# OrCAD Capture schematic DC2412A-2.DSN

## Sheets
1 PAGE1: size Custom; rev: 1
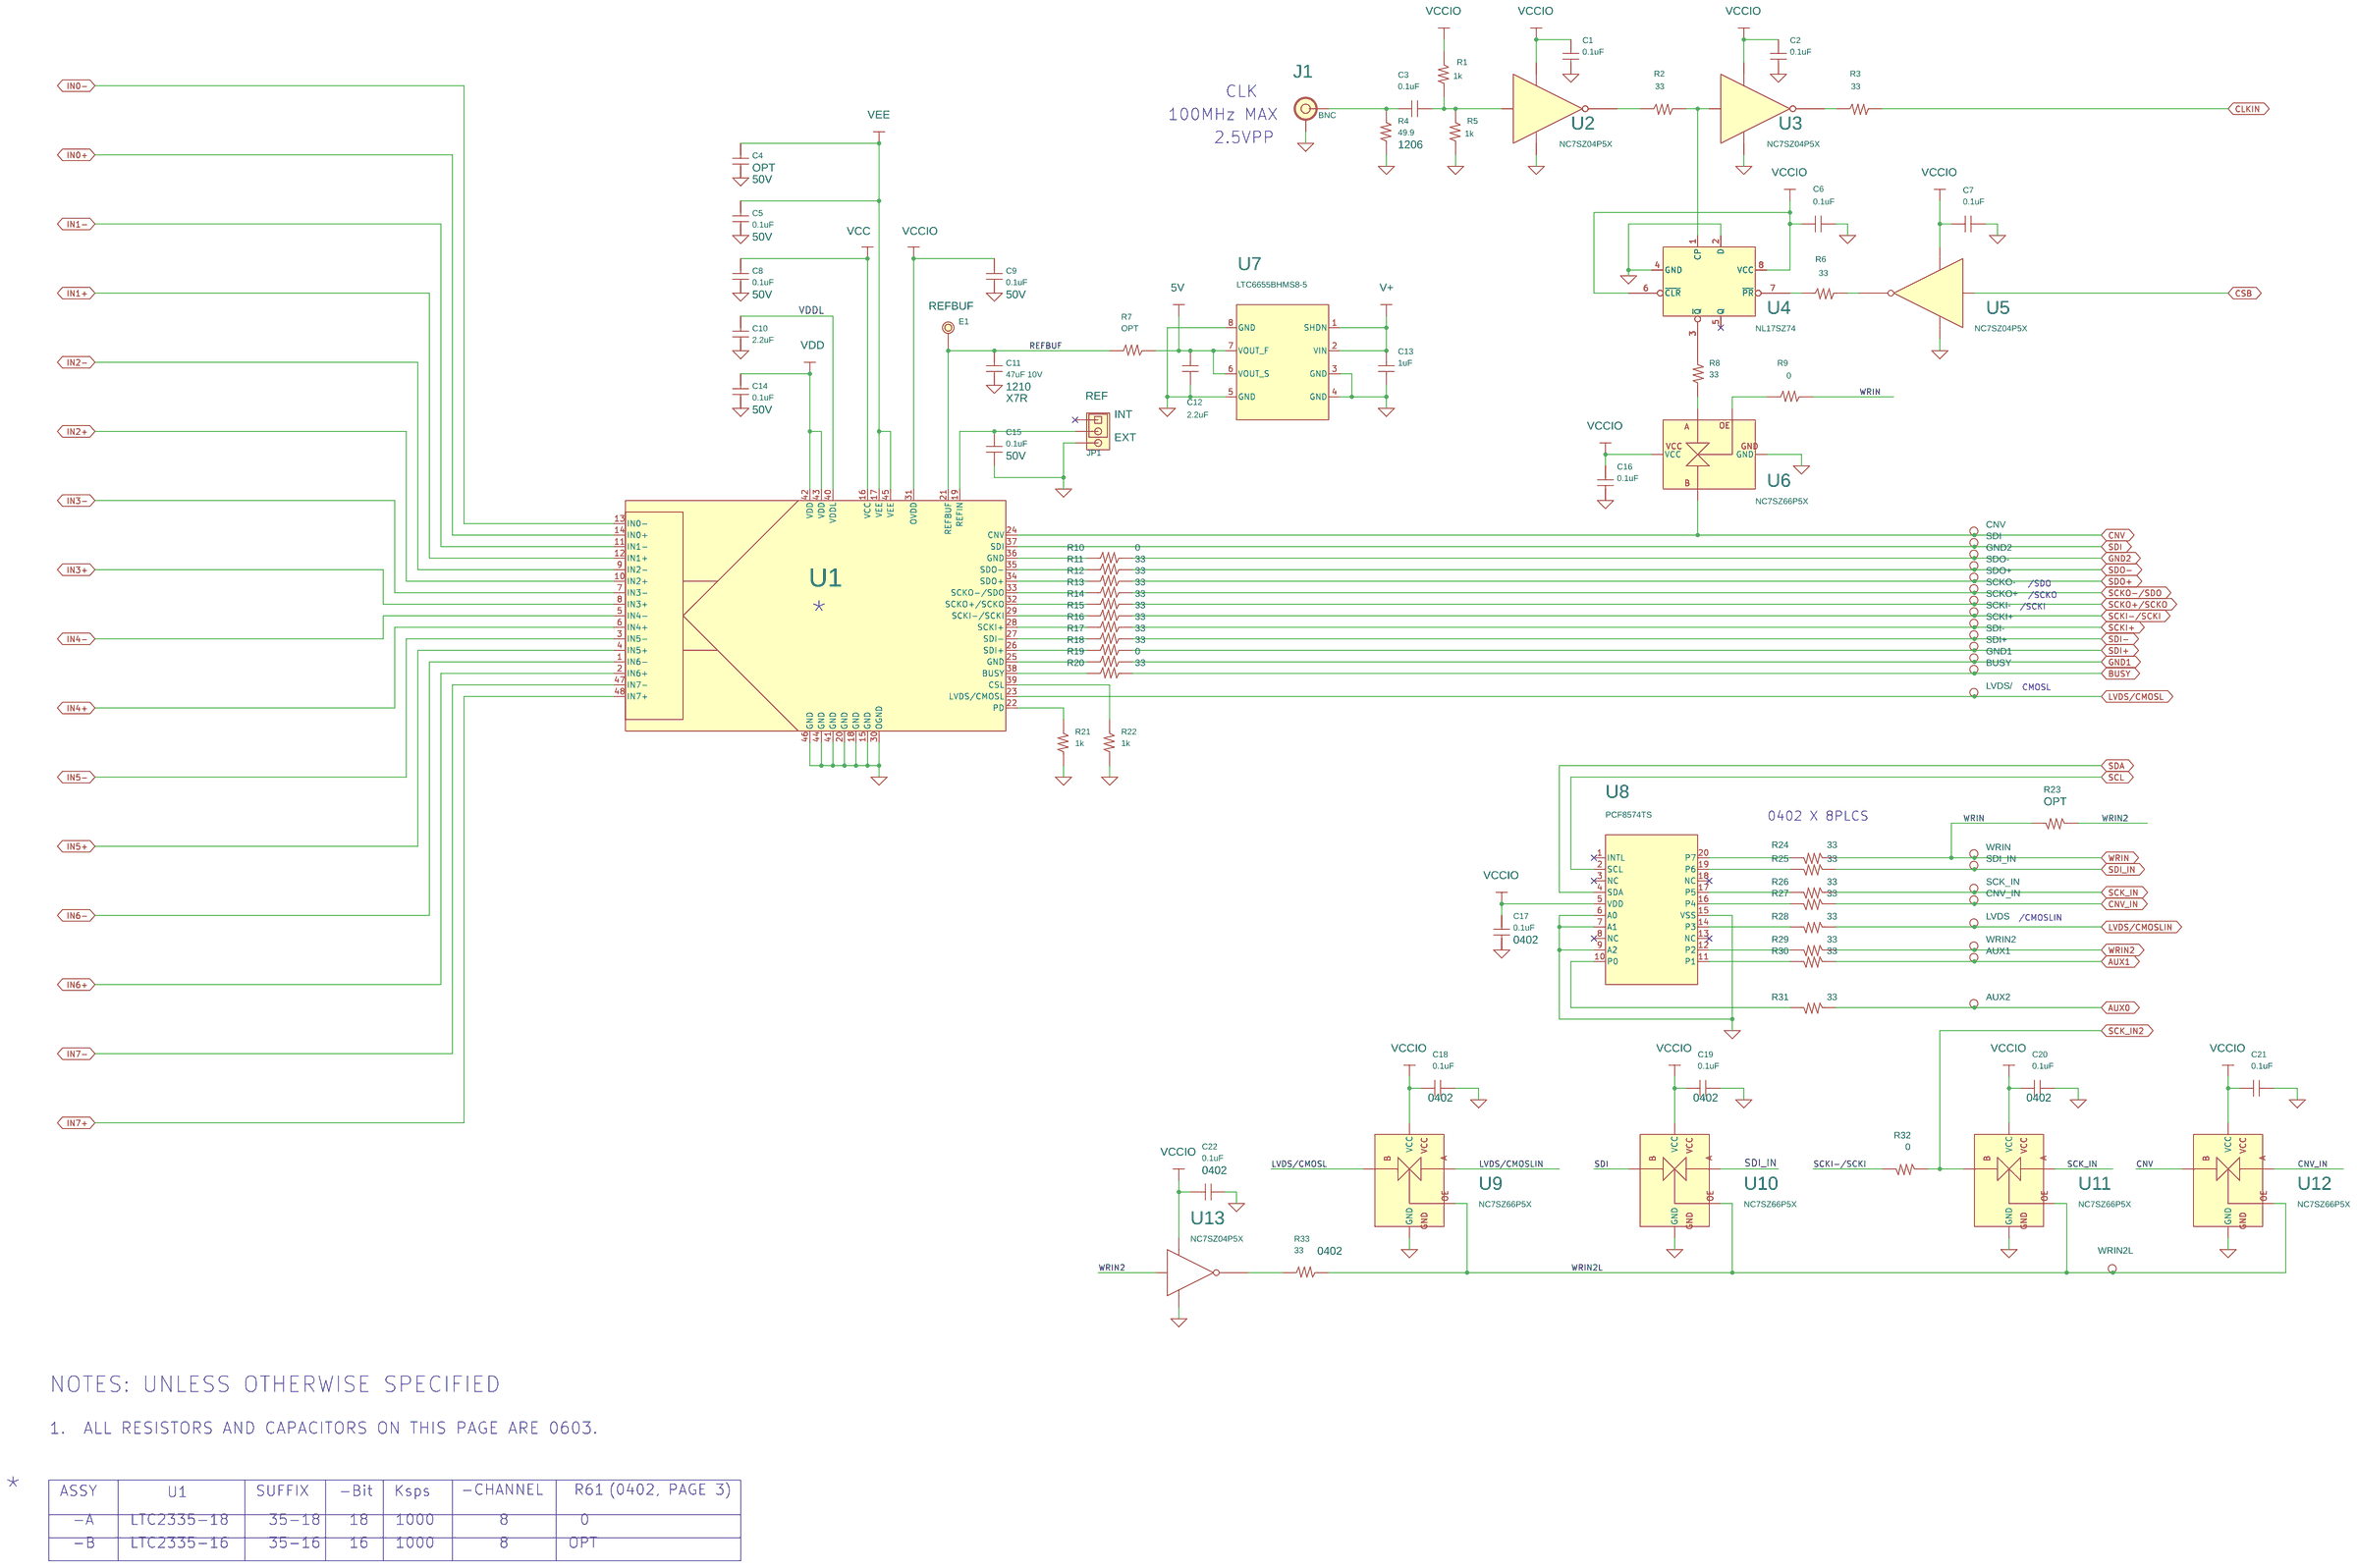
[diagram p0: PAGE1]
2 PAGE2: size B; title: 8-CHANNEL, SOFTSPAN, HIGH SPEED, SERIAL, SAR, ADC; rev: 2; company: LTC23XXILX  FAMILY; note: DEMO CIRCUIT 2412A; note: B
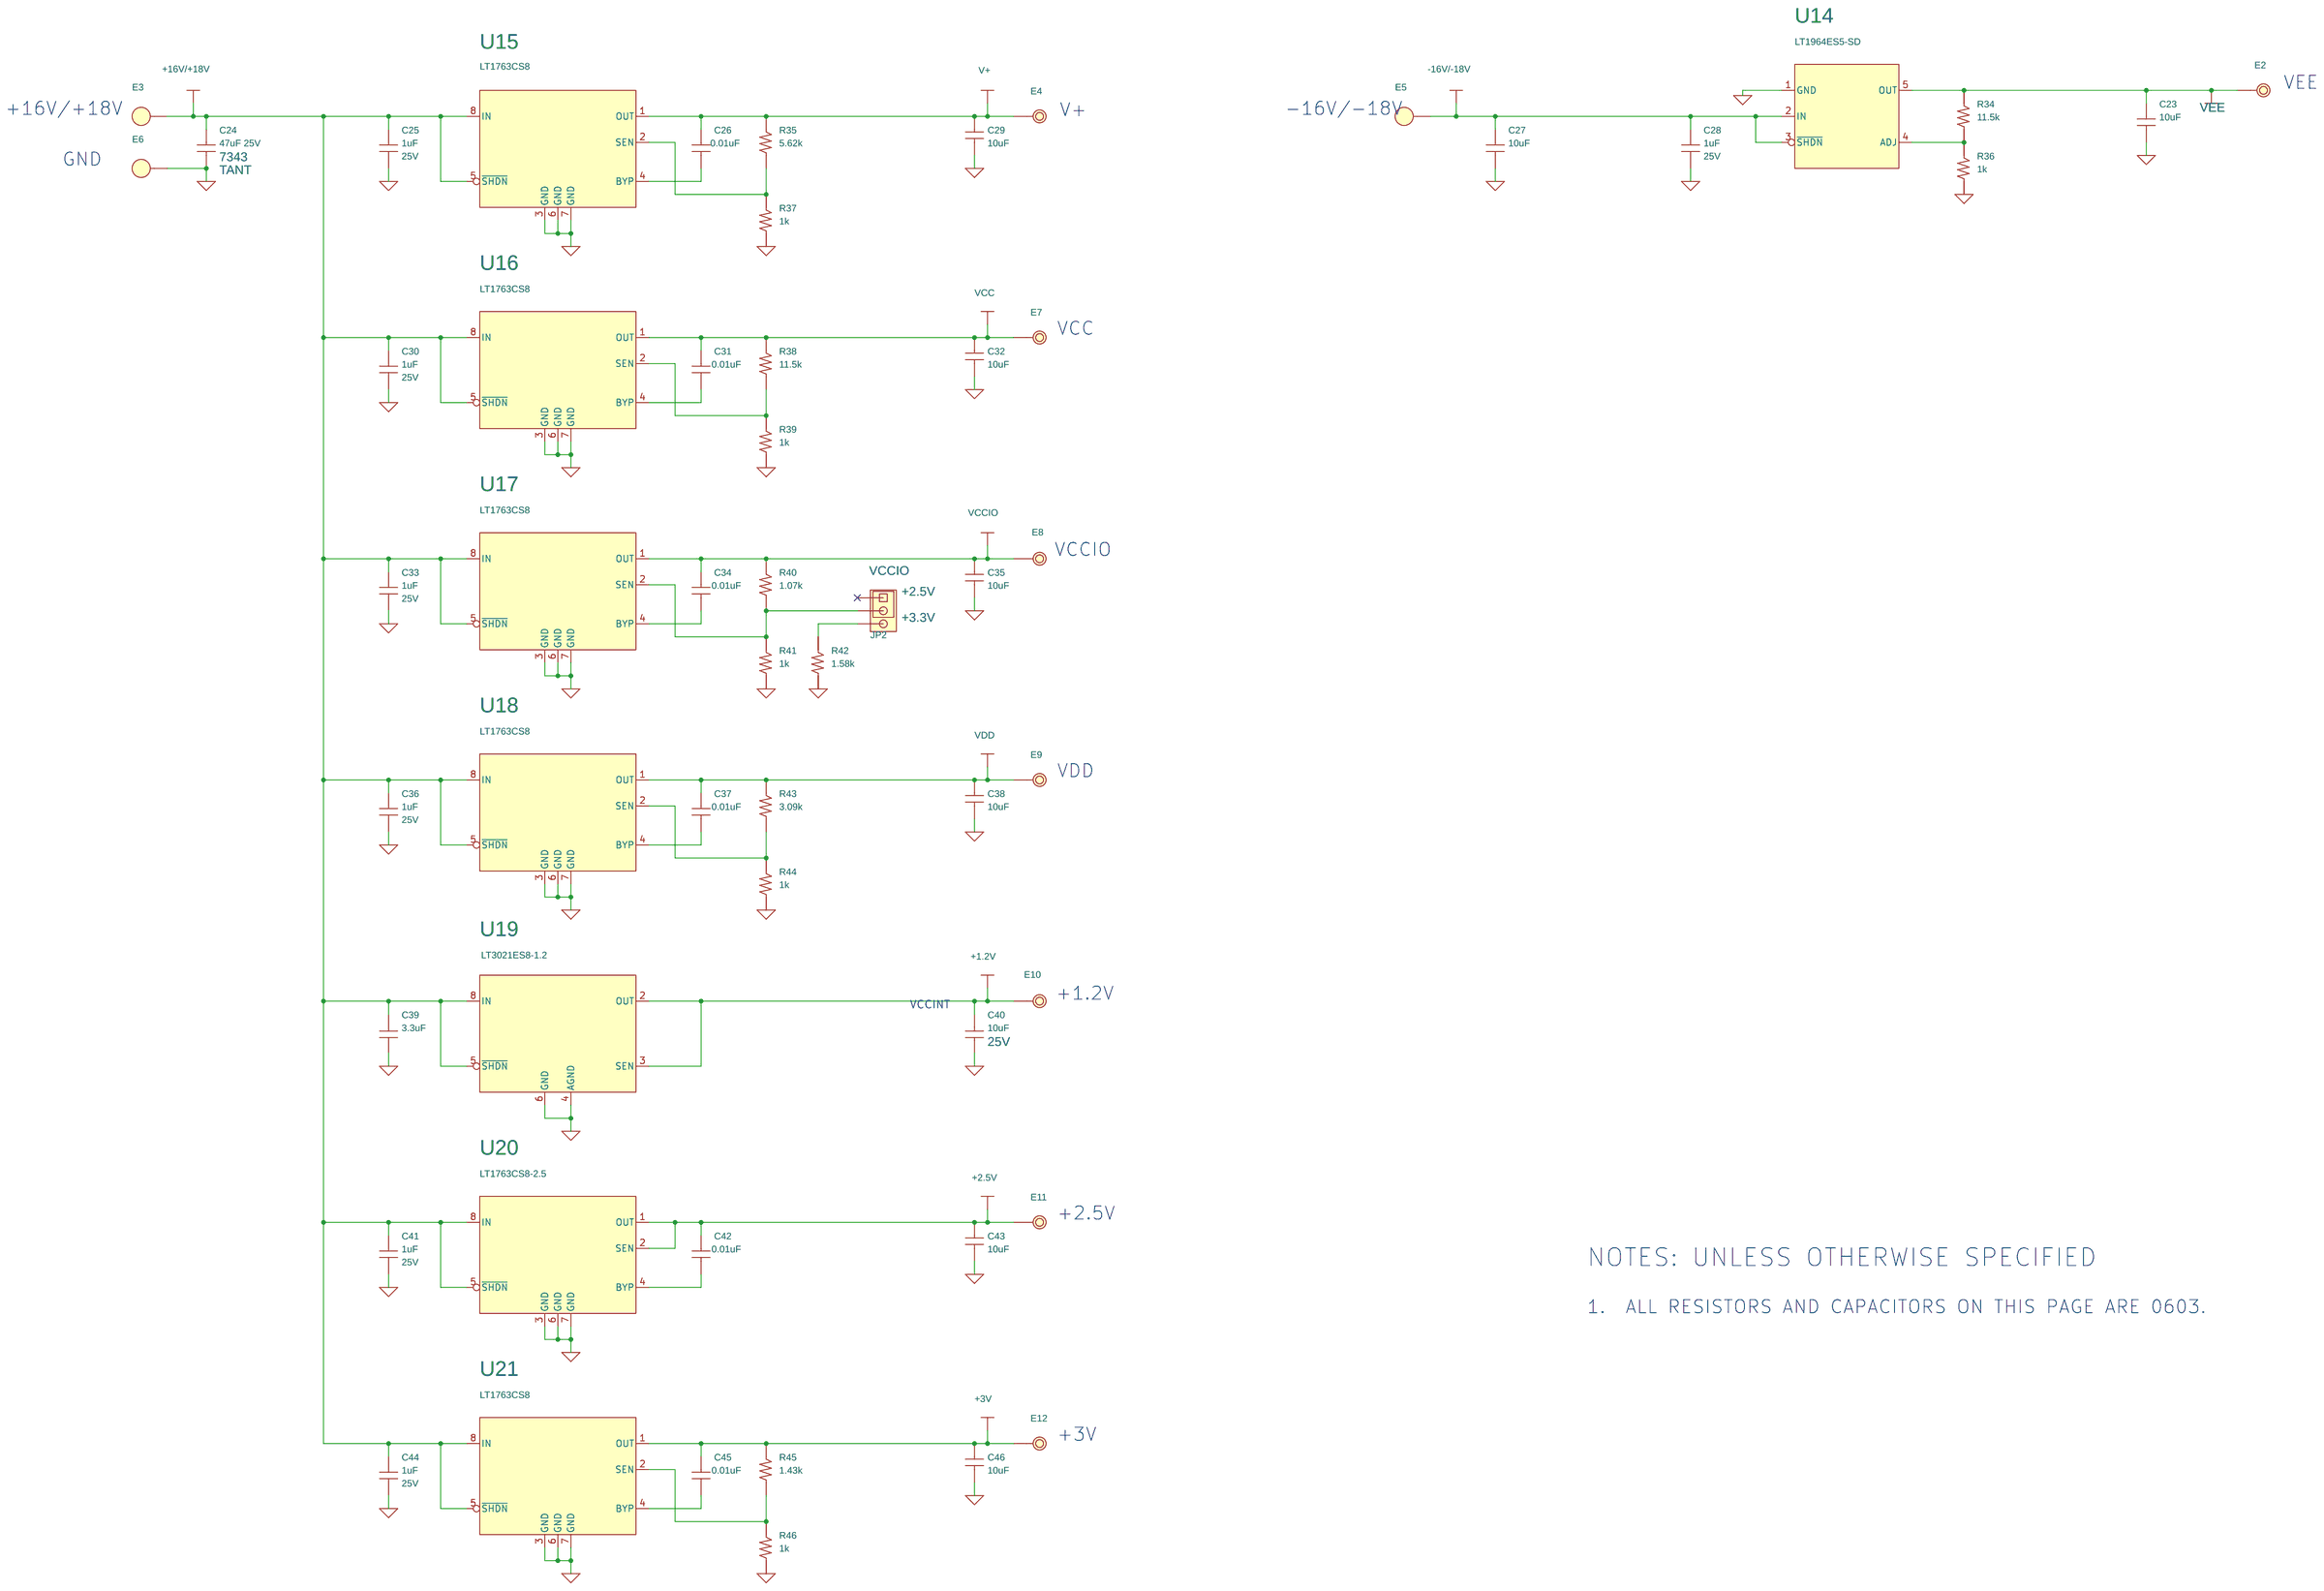
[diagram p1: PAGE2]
3 PAGE3: size B; title: 8-CHANNEL, SOFTSPAN, HIGH SPEED, SERIAL, SAR, ADC; rev: 2; company: LTC23XXILX  FAMILY; note: DEMO CIRCUIT 2412A; note: B
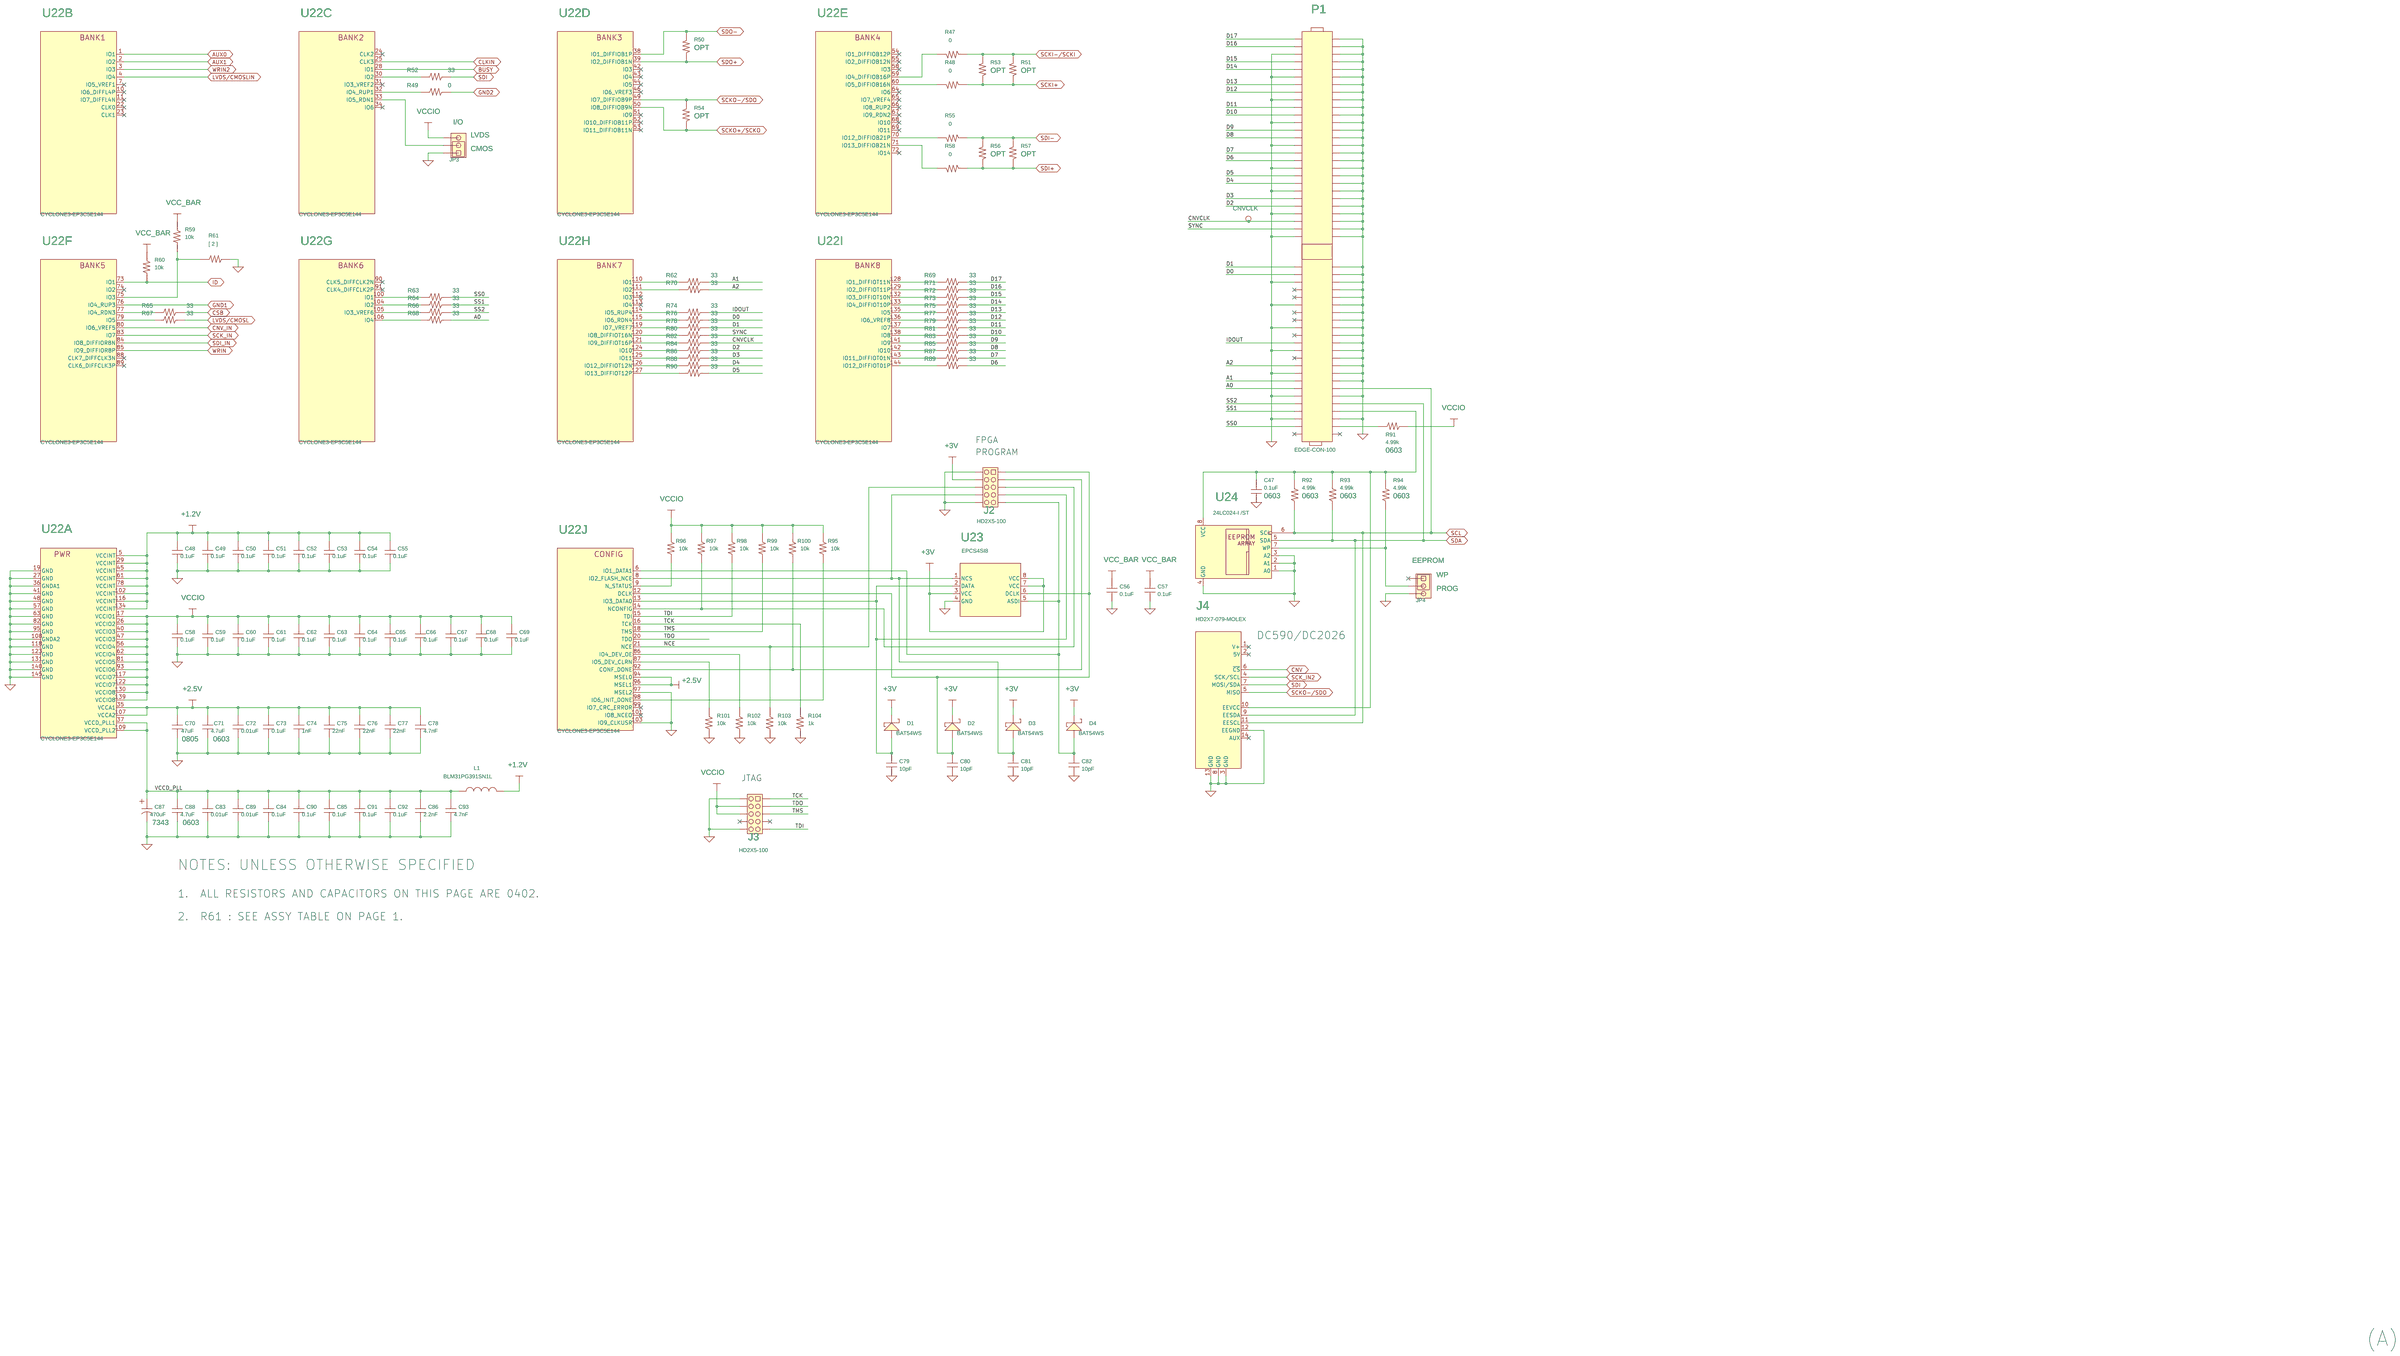
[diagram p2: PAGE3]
4 PAGE4: size B; title: 8-CHANNEL, SOFTSPAN, HIGH SPEED, SERIAL, SAR, ADC; rev: 2; company: LTC23XXILX  FAMILY; note: DEMO CIRCUIT 2412A; note: B
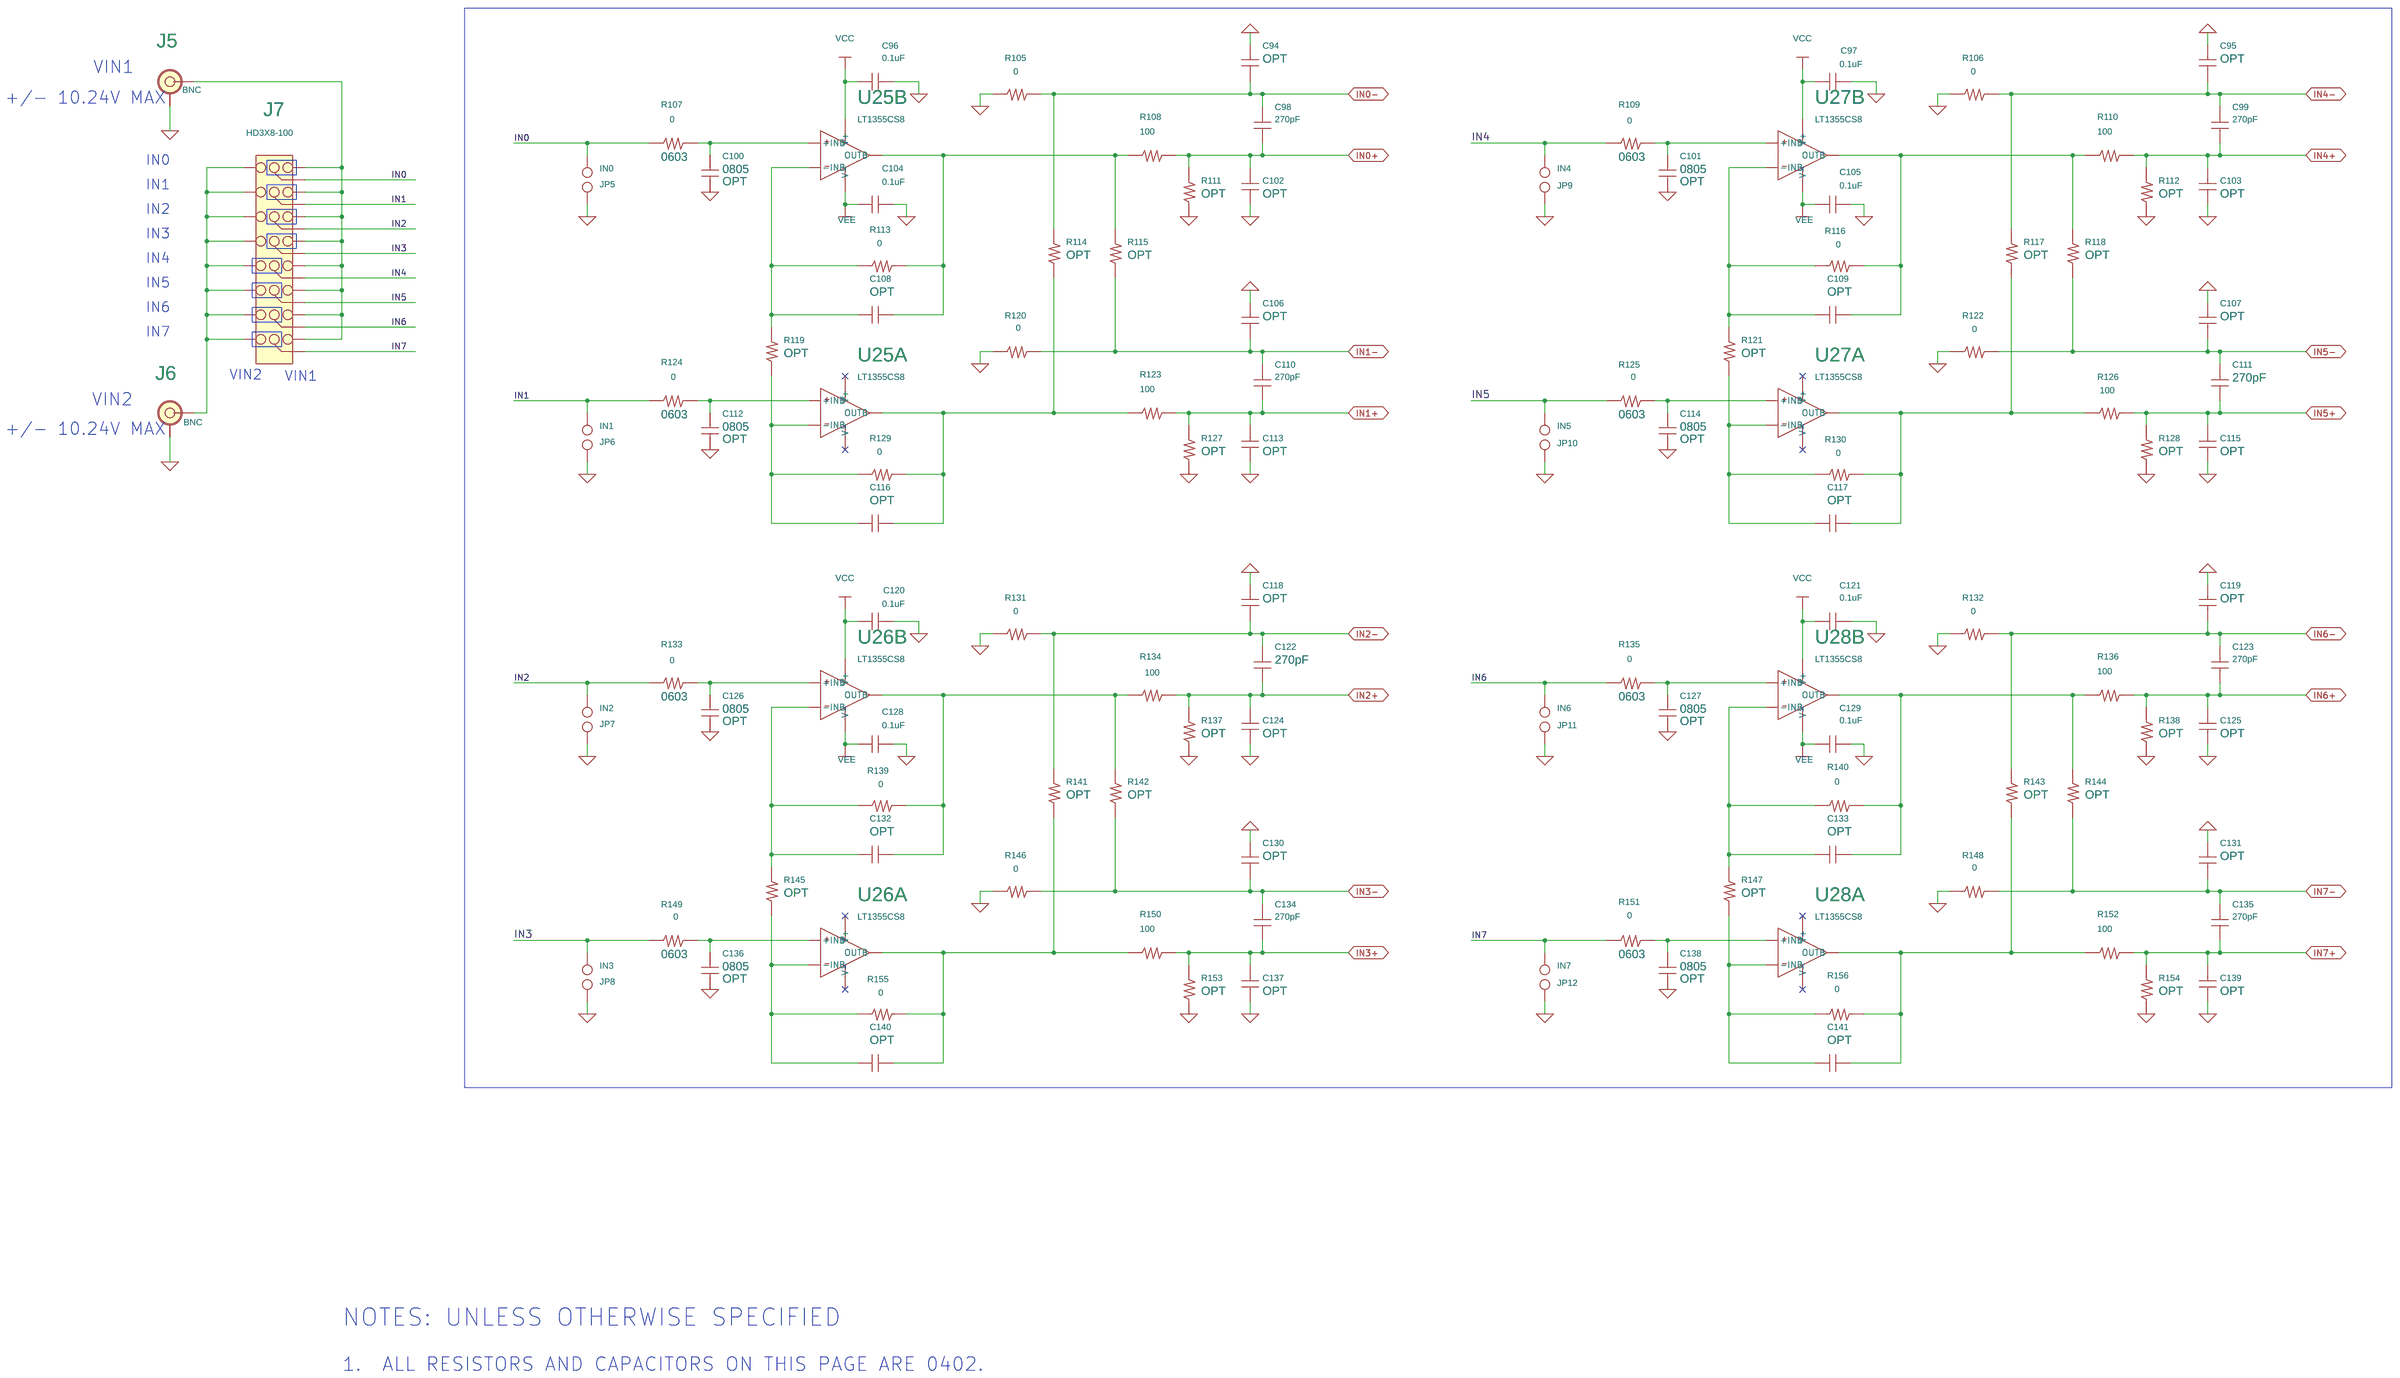
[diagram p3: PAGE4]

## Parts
sheet PAGE1
AUX1  PAD030-015-SQ  [PAD030-015-SQ]
AUX2  PAD030-015-SQ  [PAD030-015-SQ]
BUSY  PAD030-015-SQ  [PAD030-015-SQ]
C1  0.1uF  [0603]
C2  0.1uF  [0603]
C3  0.1uF  [0603]
C4  C-0603  [0603]
C5  0.1uF  [0603]
C6  0.1uF  [0603]
C7  0.1uF  [0603]
C8  0.1uF  [0603]
C9  0.1uF  [0603]
C10  2.2uF  [0603]
C11  47uF 10V  [1210]
C12  2.2uF  [0603]
C13  1uF  [0603]
C14  0.1uF  [0603]
C15  0.1uF  [0603]
C16  0.1uF  [0603]
C17  0.1uF  [0402]
C18  0.1uF  [0402]
C19  0.1uF  [0402]
C20  0.1uF  [0402]
C21  0.1uF  [0603]
C22  0.1uF  [0402]
CNV  PAD030-015-SQ  [PAD030-015-SQ]
CNV_IN  PAD030-015-SQ  [PAD030-015-SQ]
E1  MILL-MAX-2308  [MILL-MAX-2308]
GND1  PAD030-015-SQ  [PAD030-015-SQ]
GND2  PAD030-015-SQ  [PAD030-015-SQ]
J1  BNC  [BNC5]
JP1  HD1X3-100  [HD1X3-100]
LVDS  PAD030-015-SQ  [PAD030-015-SQ]
LVDS/  PAD030-015-SQ  [PAD030-015-SQ]
R1  1k  [0603]
R2  33  [0603]
R3  33  [0603]
R4  49.9  [1206]
R5  1k  [0603]
R6  33  [0603]
R7  OPT  [0603]
R8  33  [0603]
R9  0  [0603]
R10  0  [0603]
R11  33  [0603]
R12  33  [0603]
R13  33  [0603]
R14  33  [0603]
R15  33  [0603]
R16  33  [0603]
R17  33  [0603]
R18  33  [0603]
R19  0  [0603]
R20  33  [0603]
R21  1k  [0603]
R22  1k  [0603]
R23  R-0402  [0402]
R24  33  [0402]
R25  33  [0402]
R26  33  [0402]
R27  33  [0402]
R28  33  [0402]
R29  33  [0402]
R30  33  [0402]
R31  33  [0402]
R32  0  [0402]
R33  33  [0402]
SCK_IN  PAD030-015-SQ  [PAD030-015-SQ]
SCKI+  PAD030-015-SQ  [PAD030-015-SQ]
SCKI-  PAD030-015-SQ  [PAD030-015-SQ]
SCKO+  PAD030-015-SQ  [PAD030-015-SQ]
SCKO-  PAD030-015-SQ  [PAD030-015-SQ]
SDI  PAD030-015-SQ  [PAD030-015-SQ]
SDI+  PAD030-015-SQ  [PAD030-015-SQ]
SDI-  PAD030-015-SQ  [PAD030-015-SQ]
SDI_IN  PAD030-015-SQ  [PAD030-015-SQ]
SDO+  PAD030-015-SQ  [PAD030-015-SQ]
SDO-  PAD030-015-SQ  [PAD030-015-SQ]
U1  LTC2335  [LQFP48LX-7X7]
U2  NC7SZ04P5X  [SC70-5]
U3  NC7SZ04P5X  [SC70-5]
U4  NL17SZ74  [US8]
U5  NC7SZ04P5X  [SC70-5]
U6  NC7SZ66P5X  [SC70-5]
U7  LTC6655BHMS8-5  [MSOP8]
U8  PCF8574TS  [SSOP20]
U9  NC7SZ66P5X  [SC70-5]
U10  NC7SZ66P5X  [SC70-5]
U11  NC7SZ66P5X  [SC70-5]
U12  NC7SZ66P5X  [SC70-5]
U13  NC7SZ04P5X  [SC70-5]
WRIN  PAD030-015-SQ  [PAD030-015-SQ]
WRIN2  PAD030-015-SQ  [PAD030-015-SQ]
WRIN2L  PAD030-015-SQ  [PAD030-015-SQ]
sheet PAGE2
C23  10uF  [0603]
C24  47uF 25V  [7343]
C25  1uF  [0603]
C26  0.01uF  [0603]
C27  10uF  [0603]
C28  1uF  [0603]
C29  10uF  [0603]
C30  1uF  [0603]
C31  0.01uF  [0603]
C32  10uF  [0603]
C33  1uF  [0603]
C34  0.01uF  [0603]
C35  10uF  [0603]
C36  1uF  [0603]
C37  0.01uF  [0603]
C38  10uF  [0603]
C39  3.3uF  [0603]
C40  10uF  [0603]
C41  1uF  [0603]
C42  0.01uF  [0603]
C43  10uF  [0603]
C44  1uF  [0603]
C45  0.01uF  [0603]
C46  10uF  [0603]
E2  MILL-MAX-2308  [MILL-MAX-2308]
E3  MILL-MAX-2501  [MILL-MAX-2501]
E4  MILL-MAX-2308  [MILL-MAX-2308]
E5  MILL-MAX-2501  [MILL-MAX-2501]
E6  MILL-MAX-2501  [MILL-MAX-2501]
E7  MILL-MAX-2308  [MILL-MAX-2308]
E8  MILL-MAX-2308  [MILL-MAX-2308]
E9  MILL-MAX-2308  [MILL-MAX-2308]
E10  MILL-MAX-2308  [MILL-MAX-2308]
E11  MILL-MAX-2308  [MILL-MAX-2308]
E12  MILL-MAX-2308  [MILL-MAX-2308]
JP2  HD1X3-100  [HD1X3-100]
R34  11.5k  [0603]
R35  5.62k  [0603]
R36  1k  [0603]
R37  1k  [0603]
R38  11.5k  [0603]
R39  1k  [0603]
R40  1.07k  [0603]
R41  1k  [0603]
R42  1.58k  [0603]
R43  3.09k  [0603]
R44  1k  [0603]
R45  1.43k  [0603]
R46  1k  [0603]
U14  LT1964ES5-SD  [SOT23-S5]
U15  LT1763CS8  [SO8]
U16  LT1763CS8  [SO8]
U17  LT1763CS8  [SO8]
U18  LT1763CS8  [SO8]
U19  LT3021ES8-1.2  [SO8]
U20  LT1763CS8-2.5  [SO8]
U21  LT1763CS8  [SO8]
sheet PAGE3
C47  0.1uF  [0603]
C48  0.1uF  [0402]
C49  0.1uF  [0402]
C50  0.1uF  [0402]
C51  0.1uF  [0402]
C52  0.1uF  [0402]
C53  0.1uF  [0402]
C54  0.1uF  [0402]
C55  0.1uF  [0402]
C56  0.1uF  [0402]
C57  0.1uF  [0402]
C58  0.1uF  [0402]
C59  0.1uF  [0402]
C60  0.1uF  [0402]
C61  0.1uF  [0402]
C62  0.1uF  [0402]
C63  0.1uF  [0402]
C64  0.1uF  [0402]
C65  0.1uF  [0402]
C66  0.1uF  [0402]
C67  0.1uF  [0402]
C68  0.1uF  [0402]
C69  0.1uF  [0402]
C70  47uF  [0805]
C71  4.7uF  [0603]
C72  0.01uF  [0402]
C73  0.1uF  [0402]
C74  1nF  [0402]
C75  22nF  [0402]
C76  22nF  [0402]
C77  22nF  [0402]
C78  4.7nF  [0402]
C79  10pF  [0402]
C80  10pF  [0402]
C81  10pF  [0402]
C82  10pF  [0402]
C83  0.01uF  [0402]
C84  0.1uF  [0402]
C85  0.1uF  [0402]
C86  2.2nF  [0402]
C87  470uF  [7343]
C88  4.7uF  [0603]
C89  0.01uF  [0402]
C90  0.1uF  [0402]
C91  0.1uF  [0402]
C92  0.1uF  [0402]
C93  4.7nF  [0402]
CNVCLK  PAD030-015-SQ  [PAD030-015-SQ]
D1  BAT54WS  [SOD323]
D2  BAT54WS  [SOD323]
D3  BAT54WS  [SOD323]
D4  BAT54WS  [SOD323]
J2  HD2X5-100  [HD2X5-100]
J3  HD2X5-100  [HD2X5-100]
J4  HD2X7-079-MOLEX  [HD2X7-079-MOLEX]
JP3  HD1X3-100  [HD1X3-100]
JP4  HD1X3-100  [HD1X3-100]
L1  BLM31PG391SN1L  [1206]
P1  EDGE-CON-100  [CON-GOLD-100P-TB]
R47  0  [0402]
R48  0  [0402]
R49  0  [0402]
R50  R-0402  [0402]
R51  R-0402  [0402]
R52  33  [0402]
R53  R-0402  [0402]
R54  R-0402  [0402]
R55  0  [0402]
R56  R-0402  [0402]
R57  R-0402  [0402]
R58  0  [0402]
R59  10k  [0402]
R60  10k  [0402]
R61  [ 2 ]  [0402]
R62  33  [0402]
R63  33  [0402]
R64  33  [0402]
R65  33  [0402]
R66  33  [0402]
R67  33  [0402]
R68  33  [0402]
R69  33  [0402]
R70  33  [0402]
R71  33  [0402]
R72  33  [0402]
R73  33  [0402]
R74  33  [0402]
R75  33  [0402]
R76  33  [0402]
R77  33  [0402]
R78  33  [0402]
R79  33  [0402]
R80  33  [0402]
R81  33  [0402]
R82  33  [0402]
R83  33  [0402]
R84  33  [0402]
R85  33  [0402]
R86  33  [0402]
R87  33  [0402]
R88  33  [0402]
R89  33  [0402]
R90  33  [0402]
R91  4.99k  [0603]
R92  4.99k  [0603]
R93  4.99k  [0603]
R94  4.99k  [0603]
R95  10k  [0402]
R96  10k  [0402]
R97  10k  [0402]
R98  10k  [0402]
R99  10k  [0402]
R100  10k  [0402]
R101  10k  [0402]
R102  10k  [0402]
R103  10k  [0402]
R104  1k  [0402]
U22  CYCLONE3-EP3C5E144  [EQFP144]  (sections A,B,C,D,E,F,G,H,I,J)
U23  EPCS4SI8  [SO8]
U24  24LC024-I /ST  [TSSOP8]
sheet PAGE4
C94  C-0402  [0402]
C95  C-0402  [0402]
C96  0.1uF  [0402]
C97  0.1uF  [0402]
C98  270pF  [0402]
C99  270pF  [0402]
C100  C-0805  [0805]
C101  C-0805  [0805]
C102  C-0402  [0402]
C103  C-0402  [0402]
C104  0.1uF  [0402]
C105  0.1uF  [0402]
C106  C-0402  [0402]
C107  C-0402  [0402]
C108  C-0402  [0402]
C109  C-0402  [0402]
C110  270pF  [0402]
C111  270pF  [0402]
C112  C-0805  [0805]
C113  C-0402  [0402]
C114  C-0805  [0805]
C115  C-0402  [0402]
C116  C-0402  [0402]
C117  C-0402  [0402]
C118  C-0402  [0402]
C119  C-0402  [0402]
C120  0.1uF  [0402]
C121  0.1uF  [0402]
C122  270pF  [0402]
C123  270pF  [0402]
C124  C-0402  [0402]
C125  C-0402  [0402]
C126  C-0805  [0805]
C127  C-0805  [0805]
C128  0.1uF  [0402]
C129  0.1uF  [0402]
C130  C-0402  [0402]
C131  C-0402  [0402]
C132  C-0402  [0402]
C133  C-0402  [0402]
C134  270pF  [0402]
C135  270pF  [0402]
C136  C-0805  [0805]
C137  C-0402  [0402]
C138  C-0805  [0805]
C139  C-0402  [0402]
C140  C-0402  [0402]
C141  C-0402  [0402]
J5  BNC  [BNC5]
J6  BNC  [BNC5]
J7  HD3X8-100  [HD3X8-100]
JP5  HD1X2-100  [HD1X2-100]
JP6  HD1X2-100  [HD1X2-100]
JP7  HD1X2-100  [HD1X2-100]
JP8  HD1X2-100  [HD1X2-100]
JP9  HD1X2-100  [HD1X2-100]
JP10  HD1X2-100  [HD1X2-100]
JP11  HD1X2-100  [HD1X2-100]
JP12  HD1X2-100  [HD1X2-100]
R105  0  [0402]
R106  0  [0402]
R107  0  [0603]
R108  100  [0402]
R109  0  [0603]
R110  100  [0402]
R111  R-0402  [0402]
R112  R-0402  [0402]
R113  0  [0402]
R114  R-0402  [0402]
R115  R-0402  [0402]
R116  0  [0402]
R117  R-0402  [0402]
R118  R-0402  [0402]
R119  R-0402  [0402]
R120  0  [0402]
R121  R-0402  [0402]
R122  0  [0402]
R123  100  [0402]
R124  0  [0603]
R125  0  [0603]
R126  100  [0402]
R127  R-0402  [0402]
R128  R-0402  [0402]
R129  0  [0402]
R130  0  [0402]
R131  0  [0402]
R132  0  [0402]
R133  0  [0603]
R134  100  [0402]
R135  0  [0603]
R136  100  [0402]
R137  R-0402  [0402]
R138  R-0402  [0402]
R139  0  [0402]
R140  0  [0402]
R141  R-0402  [0402]
R142  R-0402  [0402]
R143  R-0402  [0402]
R144  R-0402  [0402]
R145  R-0402  [0402]
R146  0  [0402]
R147  R-0402  [0402]
R148  0  [0402]
R149  0  [0603]
R150  100  [0402]
R151  0  [0603]
R152  100  [0402]
R153  R-0402  [0402]
R154  R-0402  [0402]
R155  0  [0402]
R156  0  [0402]
U25  LT1355CS8  [SO8]  (sections A,B)
U26  LT1355CS8  [SO8]  (sections A,B)
U27  LT1355CS8  [SO8]  (sections A,B)
U28  LT1355CS8  [SO8]  (sections A,B)

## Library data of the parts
AUX1 AUX2 BUSY CNV CNV_IN CNVCLK GND1 GND2 LVDS LVDS/ SCK_IN SCKI+ SCKI- SCKO+ SCKO- SDI SDI+ SDI- SDI_IN SDO+ SDO- WRIN WRIN2 WRIN2L = E-HOLE
C1-C3 C6 C7 C10 C12 C13 C16-C22 C26 C31 C32 C34 C37 C39 C42 C45 C47-C86 C88-C93 C96-C99 C104 C105 C110 C111 C120-C123 C128 C129 C134 C135 = CAP-NP
C4 = CAP-NP: 1st Part Field: 50V; OPT: OPT
C5 C8 C9 C14 C15 = CAP-NP: 1st Part Field: 50V
C11 = CAP-NP: 1st Part Field: X7R
E1 = E-064: 1st Part Field: REFBUF
J1 = BNC: 1st Part Field: <1st Part Field>
JP1 = HD1X3: 1st Part Field: REF; 2nd Part Field: EXT; 3rd Part Field: INT
R1-R22 R24-R49 R52 R55 R58-R110 R113 R116 R120 R122-R126 R129-R136 R139 R140 R146 R148-R152 R155 R156 = R
R23 R50 R51 R53 R54 R56 R57 R111 R112 R114 R115 R117-R119 R121 R127 R128 R137 R138 R141-R145 R147 R153 R154 = R: OPT: OPT
U1 = LTC2335ILX-LQFP48LX-7X7
U2 U3 U5 = NC7SZ04P5X-ONE
U4 = NL17SZ74-US8
U6 U9-U12 = NC7SZ66P5X-SC70-5
U7 = LTC6655AHMSH-5
U8 = PCF8574TS-SSOP20
U13 = NC7SZ04P5X-SC70-5
C23 C25 C27-C30 C33 C35 C36 C38 C41 C43 C44 C46 = CAP-NP: 1ST PART FIELD: 25V
C24 = CAP-NP: 1ST PART FIELD: 16V; 2nd Part Field: TANT; 5TH PART FIELD: 1210
C40 = CAP-NP: 1st Part Field: 25V
E2 E4 E7-E12 = E-064
E3 E5 E6 = E-094
JP2 = HD1X3: 1st Part Field: VCCIO; 2nd Part Field: +3.3V; 3rd Part Field: +2.5V
U14 = LT1964ES5-SD-SOT23-5
U15-U18 U20 U21 = LT1763CS8-SO8
U19 = LT3021ES8-SO8
C87 = CAP
D1-D4 = BAT54WS-SOD323
J2 J3 = HD2X5-100_0
J4 = HD2X7-079-MOLEX
JP3 = HD1X3: 1st Part Field: I/O; 2nd Part Field: LVDS; 3rd Part Field: CMOS
JP4 = HD1X3: 1st Part Field: EEPROM; 2nd Part Field: PROG; 3rd Part Field: WP
L1 = IND
P1 = CON-EDGE-100P-TB
U22 = CYCLONE3-EP3C5E144-EQFP144
U23 = EPCS4SI8-SO8
U24 = 24LC025-I_ST
C94 C95 C100-C103 C106-C109 C112-C119 C124-C127 C130-C133 C136-C141 = CAP-NP: OPT: OPT
J5 J6 = BNC
J7 = HD3X8-100
JP5 = HD1X2-100: PART FIELD 1: IN0
JP6 = HD1X2-100: PART FIELD 1: IN1
JP7 = HD1X2-100: PART FIELD 1: IN2
JP8 = HD1X2-100: PART FIELD 1: IN3
JP9 = HD1X2-100: PART FIELD 1: IN4
JP10 = HD1X2-100: PART FIELD 1: IN5
JP11 = HD1X2-100: PART FIELD 1: IN6
JP12 = HD1X2-100: PART FIELD 1: IN7
U25-U28 = LT1355CS8-SO8

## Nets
5V: C12.2 R7.1 U7.6(VOUT_S) U7.7(VOUT_F)
+1.2V: C40.2 C48.2 C49.2 C50.2 C51.2 C52.2 C53.2 C54.2 C55.2 E10.1(A) L1.2 U19.2(OUT) U19.3(SEN) U22.5(VCCINT) U22.29(VCCINT) U22.45(VCCINT) U22.61(VCCINT) U22.78(VCCINT) U22.102(VCCINT) U22.116(VCCINT) U22.134(VCCINT)
+2.5V: C42.1 C43.1 C70.2 C71.2 C72.2 C73.2 C74.2 C75.2 C76.2 C77.2 C78.2 E11.1(A) U20.1(OUT) U20.2(SEN) U22.35(VCCA1) U22.94(MSEL0) U22.96(MSEL1) U22.107(VCCA2)
+3V: C45.1 C46.1 C56.2 C57.2 D1.1 D2.1 D3.1 D4.1 E12.1(A) J2.4 R45.1 U21.1(OUT) U23.3(VCC) U23.7(VCC) U23.8(VCC)
+16V/+18V: C24.1 C25.1 C30.1 C33.1 C36.1 C39.2 C41.1 C44.1 E3.1(A) U15.5(~{SHDN}) U15.8(IN) U16.5(~{SHDN}) U16.8(IN) U17.5(~{SHDN}) U17.8(IN) U18.5(~{SHDN}) U18.8(IN) U19.5(~{SHDN}) U19.8(IN) U20.5(~{SHDN}) U20.8(IN) U21.5(~{SHDN}) U21.8(IN)
-16V/-18V: C27.1 C28.1 E5.1(A) U14.2(IN) U14.3(~{SHDN})
GND: C1.2 C2.2 C4.1 C5.1 C6.2 C7.2 C8.1 C9.1 C10.1 C11.1 C12.1 C13.1 C14.1 C15.1 C16.2 C17.2 C18.2 C19.2 C20.2 C21.2 C22.1 C23.2 C24.2 C25.2 C27.2 C28.2 C29.2 C30.2 C32.2 C33.2 C35.2 C36.2 C38.2 C39.1 C40.1 C41.2 C43.2 C44.2 C46.2 C47.1 C48.1 C49.1 C50.1 C51.1 C52.1 C53.1 C54.1 C55.1 C56.1 C57.1 C58.1 C59.1 C60.1 C61.1 C62.1 C63.1 C64.1 C65.1 C66.1 C67.1 C68.1 C69.1 C70.1 C71.1 C72.1 C73.1 C74.1 C75.1 C76.1 C77.1 C78.1 C79.1 C80.1 C81.1 C82.1 C83.1 C84.1 C85.1 C86.1 C87.2 C88.1 C89.1 C90.1 C91.1 C92.1 C93.1 C94.1 C95.1 C96.2 C97.2 C100.2 C101.2 C102.1 C103.1 C104.2 C105.2 C106.1 C107.1 C112.2 C113.1 C114.2 C115.1 C118.1 C119.1 C120.2 C121.2 C124.1 C125.1 C126.2 C127.2 C128.2 C129.2 C130.1 C131.1 C136.2 C137.1 C138.2 C139.1 E6.1(A) J1.2 J1.3 J1.4 J1.5 J2.2 J2.10 J3.2 J3.10 J4.3(GND) J4.8(GND) J4.12(EEGND) J4.13(GND) J5.2 J5.3 J5.4 J5.5 J6.2 J6.3 J6.4 J6.5 JP1.3 JP3.1 JP4.3 JP5.2 JP6.2 JP7.2 JP8.2 JP9.2 JP10.2 JP11.2 JP12.2 P1.1 P1.3 P1.5 P1.6 P1.7 P1.9 P1.11 P1.12 P1.13 P1.15 P1.17 P1.18 P1.19 P1.21 P1.23 P1.24 P1.25 P1.27 P1.29 P1.30 P1.31 P1.33 P1.35 P1.36 P1.37 P1.39 P1.41 P1.42 P1.43 P1.45 P1.47 P1.48 P1.49 P1.51 P1.53 P1.54 P1.55 P1.57 P1.59 P1.60 P1.61 P1.63 P1.65 P1.66 P1.67 P1.69 P1.71 P1.72 P1.73 P1.75 P1.77 P1.78 P1.79 P1.81 P1.83 P1.84 P1.85 P1.89 P1.90 P1.95 P1.96 R4.2 R5.2 R21.2 R22.2 R36.2 R37.2 R39.2 R41.2 R42.2 R44.2 R46.2 R61.1 R101.2 R102.2 R103.2 R104.2 R105.1 R106.1 R111.1 R112.1 R120.1 R122.1 R127.1 R128.1 R131.1 R132.1 R137.1 R138.1 R146.1 R148.1 R153.1 R154.1 U1.15(GND) U1.18(GND) U1.20(GND) U1.30(OGND) U1.41(GND) U1.44(GND) U1.46(GND) U2.3 U3.3 U4.2(D) U4.4(GND) U5.3 U6.3(GND) U7.3(GND) U7.4(GND) U7.5(GND) U7.8(GND) U8.6(A0) U8.7(A1) U8.9(A2) U8.15(VSS) U9.3(GND) U10.3(GND) U11.3(GND) U12.3(GND) U13.3 U14.1(GND) U15.3(GND) U15.6(GND) U15.7(GND) U16.3(GND) U16.6(GND) U16.7(GND) U17.3(GND) U17.6(GND) U17.7(GND) U18.3(GND) U18.6(GND) U18.7(GND) U19.4(AGND) U19.6(GND) U20.3(GND) U20.6(GND) U20.7(GND) U21.3(GND) U21.6(GND) U21.7(GND) U22.19(GND) U22.27(GND) U22.36(GNDA1) U22.41(GND) U22.48(GND) U22.57(GND) U22.63(GND) U22.82(GND) U22.95(GND) U22.97(MSEL2) U22.103(IO9_CLKUSR) U22.108(GNDA2) U22.118(GND) U22.123(GND) U22.131(GND) U22.140(GND) U22.145(GND) U23.4(GND) U24.1(A0) U24.2(A1) U24.3(A2) U24.4(GND)
GND1: GND1.1 R19.1 U22.76(IO4_RUP3)
GND2: GND2.1 R10.1 R49.1
VCC: C8.2 C31.1 C32.1 C96.1 C97.1 C120.1 C121.1 E7.1(A) R38.1 U1.16(VCC) U16.1(OUT) U25.8(V+) U26.8(V+) U27.8(V+) U28.8(V+)
VCCD_PLL: C83.2 C84.2 C85.2 C86.2 C87.1 C88.2 C89.2 C90.2 C91.2 C92.2 C93.2 L1.1 U22.37(VCCD_PLL1) U22.109(VCCD_PLL2)
VCCIO: C1.1 C2.1 C6.1 C7.1 C9.2 C16.1 C17.1 C18.1 C19.1 C20.1 C21.1 C22.2 C34.1 C35.1 C58.2 C59.2 C60.2 C61.2 C62.2 C63.2 C64.2 C65.2 C66.2 C67.2 C68.2 C69.2 E8.1(A) J3.4 J3.6 JP3.3 R1.1 R40.1 R59.1 R60.1 R91.1 R95.1 R96.1 R97.1 R98.1 R99.1 R100.1 U1.31(OVDD) U2.5 U3.5 U4.6(~{CLR}) U4.8(VCC) U5.5 U6.5(VCC) U8.5(VDD) U9.5(VCC) U10.5(VCC) U11.5(VCC) U12.5(VCC) U13.5 U17.1(OUT) U22.17(VCCIO1) U22.26(VCCIO2) U22.40(VCCIO3) U22.47(VCCIO3) U22.56(VCCIO4) U22.62(VCCIO4) U22.81(VCCIO5) U22.93(VCCIO6) U22.117(VCCIO7) U22.122(VCCIO7) U22.130(VCCIO8) U22.139(VCCIO8)
VDD: C14.2 C37.1 C38.1 E9.1(A) R43.1 U1.42(VDD) U1.43(VDD) U18.1(OUT)
VDDL: C10.2 U1.40(VDDL)
VEE: C4.2 C5.2 C23.1 C104.1 C105.1 C128.1 C129.1 E2.1(A) R34.1 U1.17(VEE) U1.45(VEE) U14.5(OUT) U25.4(V-) U26.4(V-) U27.4(V-) U28.4(V-)
A0: P1.88 R68.1
A1: P1.86 R62.1
A2: P1.82 R70.1
AUX0: AUX2.1 R31.1 U22.1(IO1)
AUX1: AUX1.1 R30.1 U22.2(IO2)
BUSY: BUSY.1 R20.1 U22.28(IO1)
CLKIN: R3.2 U22.25(CLK3)
CNV: CNV.1 J4.6(~{CS}) U1.24(CNV) U6.2 U12.2
CNV_IN: CNV_IN.1 R27.1 U12.1 U22.80(IO6_VREF5)
CNVCLK: CNVCLK.1 P1.50 R82.1
CSB: R65.1 U5.2
D0: P1.58 R76.1
D1: P1.56 R78.1
D2: P1.46 R84.1
D3: P1.44 R86.1
D4: P1.40 R88.1
D5: P1.38 R90.1
D6: P1.34 R89.1
D7: P1.32 R87.1
D8: P1.28 R85.1
D9: P1.26 R83.1
D10: P1.22 R81.1
D11: P1.20 R79.1
D12: P1.16 R77.1
D13: P1.14 R75.1
D14: P1.10 R73.1
D15: P1.8 R72.1
D16: P1.4 R71.1
D17: P1.2 R69.1
ID: R60.2 U22.73(IO1)
IDOUT: P1.76 R74.1
IN0: J7.9 JP5.1 R107.1
IN0+: C98.1 C102.2 R108.2 R111.2 U1.14(IN0+)
IN0-: C94.2 C98.2 R105.2 R114.2 U1.13(IN0-)
IN1: J7.10 JP6.1 R124.1
IN1+: C110.1 C113.2 R123.2 R127.2 U1.12(IN1+)
IN1-: C106.2 C110.2 R115.1 R120.2 U1.11(IN1-)
IN2: J7.11 JP7.1 R133.1
IN2+: C122.1 C124.2 R134.2 R137.2 U1.10(IN2+)
IN2-: C118.2 C122.2 R131.2 R141.2 U1.9(IN2-)
IN3: J7.12 JP8.1 R149.1
IN3+: C134.1 C137.2 R150.2 R153.2 U1.8(IN3+)
IN3-: C130.2 C134.2 R142.1 R146.2 U1.7(IN3-)
IN4: J7.13 JP9.1 R109.1
IN4+: C99.1 C103.2 R110.2 R112.2 U1.6(IN4+)
IN4-: C95.2 C99.2 R106.2 R117.2 U1.5(IN4-)
IN5: J7.14 JP10.1 R125.1
IN5+: C111.1 C115.2 R126.2 R128.2 U1.4(IN5+)
IN5-: C107.2 C111.2 R118.1 R122.2 U1.3(IN5-)
IN6: J7.15 JP11.1 R135.1
IN6+: C123.1 C125.2 R136.2 R138.2 U1.2(IN6+)
IN6-: C119.2 C123.2 R132.2 R143.2 U1.1(IN6-)
IN7: J7.16 JP12.1 R151.1
IN7+: C135.1 C139.2 R152.2 R154.2 U1.48(IN7+)
IN7-: C131.2 C135.2 R144.1 R148.2 U1.47(IN7-)
LVDS/CMOSL: LVDS/.1 R67.1 U1.23(LVDS/CMOSL) U9.2
LVDS/CMOSLIN: LVDS.1 R28.1 U9.1 U22.4(IO4)
NCE: J2.6 R103.1 U22.21(NCE)
REFBUF: C11.2 E1.1(A) R7.2 U1.21(REFBUF)
SCK_IN: R26.1 SCK_IN.1 U11.1 U22.83(IO7)
SCK_IN2: J4.4(SCK/SCL) R32.1 U11.2
SCKI+: R16.1 R48.1 R51.1 R53.1 SCKI+.1
SCKI-/SCKI: R15.1 R32.2 R47.1 R51.2 R53.2 SCKI-.1
SCKO+/SCKO: R14.1 R54.1 SCKO+.1 U22.50(IO8_DIFFIOB9N)
SCKO-/SDO: J4.5(MISO) R13.1 R54.2 SCKO-.1 U22.49(IO7_DIFFIOB9P)
SCL: J4.11(EESCL) P1.87 R92.1 U8.2(SCL) U24.6(SCL)
SDA: J4.9(EESDA) P1.91 R93.1 U8.4(SDA) U24.5(SDA)
SDI: J4.7(MOSI/SDA) R52.1 SDI.1 U1.37(SDI) U10.2
SDI+: R18.1 R56.1 R57.1 R58.1 SDI+.1
SDI-: R17.1 R55.1 R56.2 R57.2 SDI-.1
SDI_IN: R25.1 SDI_IN.1 U10.1 U22.84(IO8_DIFFIOR8N)
SDO+: R12.1 R50.1 SDO+.1 U22.39(IO2_DIFFIOB1N)
SDO-: R11.1 R50.2 SDO-.1 U22.38(IO1_DIFFIOB1P)
SS0: P1.98 R63.1
SS1: P1.94 R64.1
SS2: P1.92 R66.1
SYNC: P1.52 R80.1
TCK: J3.1 R104.1 U22.16(TCK)
TDI: J3.9 R98.2 U22.15(TDI)
TDO: J3.3 U22.20(TDO)
TMS: J3.5 R99.2 U22.18(TMS)
V+: C13.2 C26.1 C29.1 E4.1(A) R35.1 U7.1(SHDN) U7.2(VIN) U15.1(OUT)
WRIN: R9.1 R23.2 R24.1 U22.85(IO9_DIFFIOR8P) WRIN.1
WRIN2: R23.1 R29.1 U13.2 U22.3(IO3) WRIN2.1
WRIN2L: R33.1 U9.4 U10.4 U11.4 U12.4 WRIN2L.1
N928027: C3.2 R1.2 R5.1 U2.2
N928109: C3.1 J1.1 R4.1
N928437: R2.2 U3.2 U4.1(CP)
N929285: R6.1 U4.7(~{PR})
N940093: C34.2 U17.4(BYP)
N940147: JP2.2 R40.2 R41.1 U17.2(SEN)
N979025: R3.1 U3.4
N1083481: R6.2 U5.4
N4126329: R35.2 R37.1 U15.2(SEN)
N4126471: C26.2 U15.4(BYP)
N4148550: C37.2 U18.4(BYP)
N4148570: R43.2 R44.1 U18.2(SEN)
N5992639: R21.1 U1.22(PD)
N5993083: R22.1 U1.39(CSL)
N6131415: C15.2 JP1.2 U1.19(REFIN)
N7163907: C100.1 R107.2 U25.5(+INB)
N7164077: C108.2 R108.1 R113.2 R115.2 U25.7(OUTB)
N7164437: C112.1 R124.2 U25.3(+INB)
N7164481: C108.1 R113.1 R119.2 U25.6(-INB)
N9606066: R10.2 U1.36(GND)
N9606989: R11.2 U1.35(SDO-)
N9609820: R12.2 U1.34(SDO+)
N9609836: R13.2 U1.33(SCKO-/SDO)
N9610867: R14.2 U1.32(SCKO+/SCKO)
N9610883: R15.2 U1.29(SCKI-/SCKI)
N9611920: R16.2 U1.28(SCKI+)
N9611936: R17.2 U1.27(SDI-)
N9612979: R18.2 U1.26(SDI+)
N9612995: R19.2 U1.25(GND)
N9614029: R20.2 U1.38(BUSY)
N9659090: R9.2 U6.4
N10801258: C42.2 U20.4(BYP)
N10809399: R45.2 R46.1 U21.2(SEN)
N10809527: C45.2 U21.4(BYP)
N10819774: R38.2 R39.1 U16.2(SEN)
N10819902: C31.2 U16.4(BYP)
N10825550: R34.2 R36.1 U14.4(ADJ)
N10881449: J2.3 R100.2 U22.92(CONF_DONE)
N10881623: R95.2 U22.98(IO6_INIT_DONE)
N10881677: C81.2 D3.2 J2.8 U22.8(IO2_FLASH_NCE) U23.1(NCS)
N10881707: R84.2 U22.124(IO10)
N10881711: R86.2 U22.125(IO11)
N10881735: R90.2 U22.127(IO13_DIFFIOT12P)
N10882057: C79.2 D1.2 J2.7 U22.13(IO3_DATA0) U23.2(DATA)
N10882603: C80.2 D2.2 J2.1 U22.12(DCLK) U23.6(DCLK)
N10883255: C82.2 D4.2 J2.9 U22.6(IO1_DATA1) U23.5(ASDI)
N10884549: R88.2 U22.126(IO12_DIFFIOT12N)
N10885053: J2.5 R97.2 U22.14(NCONFIG)
N10885699: R101.1 U22.87(IO5_DEV_CLRN)
N10885829: R96.2 U22.9(N_STATUS)
N10885885: R102.1 U22.86(IO4_DEV_OE)
N10891445: C47.2 J4.10(EEVCC) P1.93 R92.2 R93.2 R94.2 U24.8(VCC)
N10891855: JP4.2 R94.1 U24.7(WP)
N10892093: P1.97 R91.2
N10957562: R52.2 U22.30(IO2)
N10970394: R49.2 U22.32(IO4_RUP1)
N10997996: JP3.2 U22.33(IO5_RDN1)
N11046555: R47.2 U22.59(IO4_DIFFIOB16P)
N11065782: R48.2 U22.60(IO5_DIFFIOB16N)
N11089379: R55.2 U22.70(IO12_DIFFIOB21P)
N11090651: R58.2 U22.71(IO13_DIFFIOB21N)
N11127617: R65.2 U22.77(IO4_RDN3)
N11127621: R67.2 U22.79(IO5)
N11197847: R68.2 U22.106(IO4)
N11197851: R66.2 U22.105(IO3_VREF6)
N11198954: R64.2 U22.104(IO2)
N11198958: R63.2 U22.100(IO1)
N11221301: R76.2 U22.115(IO6_RDN4)
N11221305: R78.2 U22.119(IO7_VREF7)
N11221309: R82.2 U22.121(IO9_DIFFIOT16P)
N11221337: R80.2 U22.120(IO8_DIFFIOT16N)
N11222408: R74.2 U22.114(IO5_RUP4)
N11224534: R70.2 U22.111(IO2)
N11224560: R62.2 U22.110(IO1)
N11274502: R71.2 U22.129(IO2_DIFFIOT11P)
N11274528: R69.2 U22.128(IO1_DIFFIOT11N)
N11279563: R73.2 U22.133(IO4_DIFFIOT10P)
N11279587: R72.2 U22.132(IO3_DIFFIOT10N)
N11280655: R77.2 U22.136(IO6_VREF8)
N11280679: R75.2 U22.135(IO5)
N11281755: R81.2 U22.138(IO8)
N11281779: R79.2 U22.137(IO7)
N11282863: R85.2 U22.142(IO10)
N11282887: R83.2 U22.141(IO9)
N11283979: R89.2 U22.144(IO12_DIFFIOT01P)
N11284003: R87.2 U22.143(IO11_DIFFIOT01N)
N11317172: R24.2 U8.20(P7)
N11317192: R25.2 U8.19(P6)
N11317212: R26.2 U8.17(P5)
N11317272: R27.2 U8.16(P4)
N11317308: R28.2 U8.14(P3)
N11317424: R29.2 U8.12(P2)
N11317448: R30.2 U8.11(P1)
N11317468: R31.2 U8.10(P0)
N11684985: R33.2 U13.4
N12089373: R59.2 R61.2 U22.75(IO3)
N12776393: R8.1 U6.1
N12850146: R2.1 U2.4
N15670275: JP2.3 R42.1
N15702031: C116.2 R114.1 R123.1 R129.2 U25.1(OUTB)
N15702135: C116.1 R119.1 R129.1 U25.2(-INB)
N17132397: C140.2 R141.1 R150.1 R155.2 U26.1(OUTB)
N17132407: C132.1 R139.1 R145.2 U26.6(-INB)
N17132409: C140.1 R145.1 R155.1 U26.2(-INB)
N17132482: C136.1 R149.2 U26.3(+INB)
N17132484: C132.2 R134.1 R139.2 R142.2 U26.7(OUTB)
N17132567: C126.1 R133.2 U26.5(+INB)
N17133719: C117.2 R117.1 R126.1 R130.2 U27.1(OUTB)
N17133729: C109.1 R116.1 R121.2 U27.6(-INB)
N17133731: C117.1 R121.1 R130.1 U27.2(-INB)
N17133804: C114.1 R125.2 U27.3(+INB)
N17133806: C109.2 R110.1 R116.2 R118.2 U27.7(OUTB)
N17133889: C101.1 R109.2 U27.5(+INB)
N17135133: C141.2 R143.1 R152.1 R156.2 U28.1(OUTB)
N17135143: C133.1 R140.1 R147.2 U28.6(-INB)
N17135145: C141.1 R147.1 R156.1 U28.2(-INB)
N17135218: C138.1 R151.2 U28.3(+INB)
N17135220: C133.2 R136.1 R140.2 R144.2 U28.7(OUTB)
N17135303: C127.1 R135.2 U28.5(+INB)
N17163895: J6.1 J7.1 J7.2 J7.3 J7.4 J7.5 J7.6 J7.7 J7.8
N17170303: J5.1 J7.17 J7.18 J7.19 J7.20 J7.21 J7.22 J7.23 J7.24
N18641882: R8.2 U4.3(~{Q})

Not connected (* = marked no-connect by the designer): J3 7* 8*; J4 1(V+)* 2(5V)* 14(AUX)*; JP1 1*; JP2 1*; JP4 1*; P1 62* 64* 68* 70* 74* 80* 99* 100*; U4 5(Q)*; U8 1(INTL)* 3(NC)* 8(NC)* 13(NC)* 18(NC)*; U22 7(IO5_VREF1)* 10(IO6_DIFFL4P)* 11(IO7_DIFFL4N)* 22(CLK0)* 23(CLK1)* 24(CLK2)* 31(IO3_VREF2)* 34(IO6)* 42(IO3)* 43(IO4)* 44(IO5)* 46(IO6_VREF3)* 51(IO9)* 52(IO10_DIFFIOB11P)* 53(IO11_DIFFIOB11N)* 54(IO1_DIFFIOB12P)* 55(IO2_DIFFIOB12N)* 58(IO3)* 64(IO6)* 65(IO7_VREF4)* 66(IO8_RUP2)* 67(IO9_RDN2)* 68(IO10)* 69(IO11)* 72(IO14)* 74(IO2)* 88(CLK7_DIFFCLK3N)* 89(CLK6_DIFFCLK3P)* 90(CLK5_DIFFCLK2N)* 91(CLK4_DIFFCLK2P)* 99(IO7_CRC_ERROR)* 101(IO8_NCEO)* 112(IO3)* 113(IO4)*

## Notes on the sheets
sheet 1
- CLK
- 100MHz MAX
- 2.5VPP
- /SDO
- /SCKO
- *
- /SCKI
- CMOSL
- 0402 X 8PLCS
- /CMOSLIN
- NOTES: UNLESS OTHERWISE SPECIFIED
- 1.  ALL RESISTORS AND CAPACITORS ON THIS PAGE ARE 0603.
- *
- ASSY
- U1
- SUFFIX
- -Bit
- Ksps
- -CHANNEL
- R61
- (0402, PAGE 3)
- -A
- LTC2335-18
- 35-18
- 18
- 1000
- 8
- 0
- -B
- LTC2335-16
- 35-16
- 16
- 1000
- 8
- OPT
sheet 2
- VEE
- +16V/+18V
- V+
- -16V/-18V
- GND
- VCC
- VCCIO
- VDD
- +1.2V
- VCCINT
- +2.5V
- NOTES: UNLESS OTHERWISE SPECIFIED
- 1.  ALL RESISTORS AND CAPACITORS ON THIS PAGE ARE 0603.
- +3V
sheet 3
- FPGA
- PROGRAM
- DC590/DC2026
- JTAG
- NOTES: UNLESS OTHERWISE SPECIFIED
- 1.  ALL RESISTORS AND CAPACITORS ON THIS PAGE ARE 0402.
- 2.  R61 : SEE ASSY TABLE ON PAGE 1.
- (A)
sheet 4
- VIN1
- +/- 10.24V MAX
- IN0
- IN1
- IN2
- IN3
- IN4
- IN5
- IN6
- IN7
- VIN2
- VIN1
- VIN2
- +/- 10.24V MAX
- NOTES: UNLESS OTHERWISE SPECIFIED
- 1.  ALL RESISTORS AND CAPACITORS ON THIS PAGE ARE 0402.
